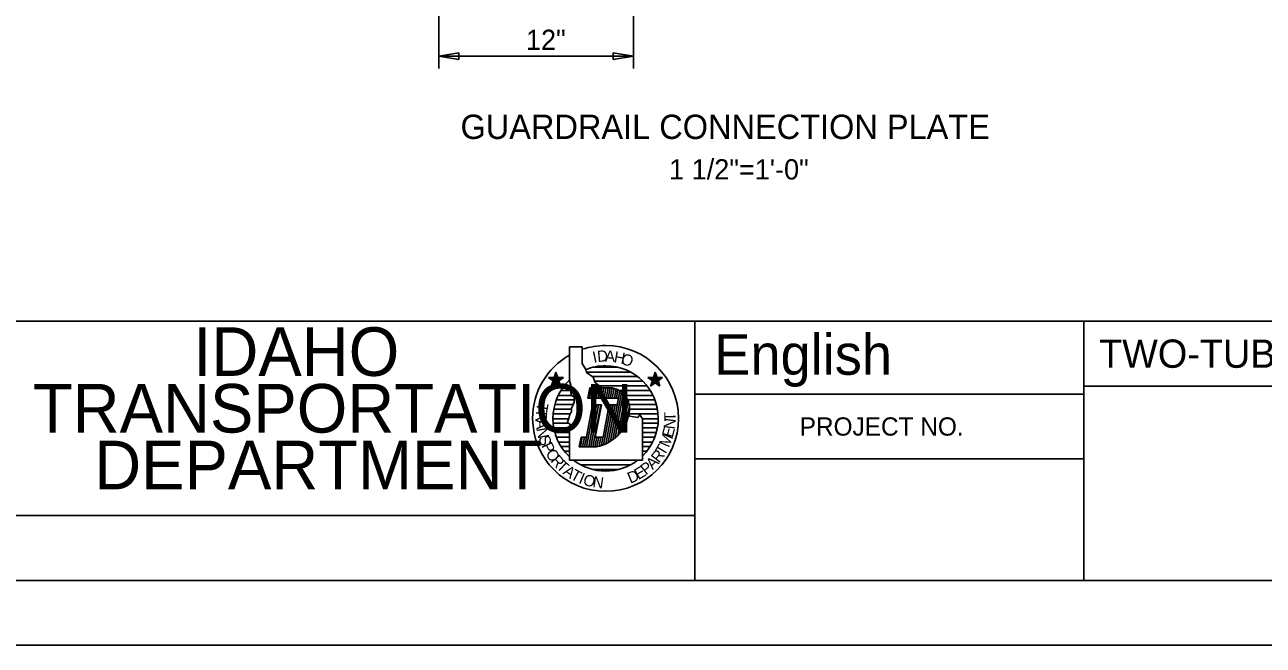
# Model space of a CAD drawing. Extents: x 0 to 22.7, y 0 to 15.7.
# Drawn here: x 9.39 to 15.76, y 0 to 3.19 of the extents above; entities that cross this region are included whole.
import ezdxf

# ---------------------------------------------------------------- set-up
doc = ezdxf.new("R2010")
doc.units = 0
for name, color, linetype in [('BORDER_ANNO_Cutsheet', 7, 'Continuous'), ('BRDG_ANNO_Anno-Sheet', 7, 'Continuous'), ('BRDG_ANNO_General-Notes', 7, 'Continuous')]:
    doc.layers.add(name, color=color, linetype=linetype)

msp = doc.modelspace()

# ---------------------------------------------------------------- linework, layer by layer
at = {"layer": 'BORDER_ANNO_Cutsheet'}
msp.add_lwpolyline([(0, 14.6667), (22.6667, 14.6667), (22.6667, 0), (0, 0)], close=True, dxfattribs=at)
at = {"layer": 'BRDG_ANNO_Anno-Sheet'}
for p, q in [((1, 1.6667), (12.8333, 1.6667)), ((12.8333, 0.3333), (12.8333, 1.6667)), ((12.8333, 1.6667), (22.3333, 1.6667)), ((14.8333, 0.3333), (14.8333, 1.6667)), ((12.1896, 1.3617), (12.1896, 1.5354)), ((12.1896, 1.5354), (12.2554, 1.5354)), ((12.2554, 1.4487), (12.2554, 1.5354)), ((12.1104, 1.3771), (12.1196, 1.4046)), ((12.1196, 1.3492), (12.1196, 1.4046)), ((12.1288, 1.3771), (12.1196, 1.4046)), ((12.2554, 1.4487), (12.2729, 1.4175)), ((12.2729, 1.4175), (12.2762, 1.4033)), ((12.2762, 1.4033), (12.3108, 1.3792)), ((12.2779, 1.4054), (12.5004, 1.4054)), ((12.31, 1.4296), (12.4387, 1.4296)), ((12.6212, 1.3771), (12.6304, 1.4046)), ((12.6304, 1.3492), (12.6304, 1.4046)), ((12.6396, 1.3771), (12.6304, 1.4046)), ((12.1342, 1.36), (12.0817, 1.3771)), ((12.1104, 1.3771), (12.0817, 1.3771)), ((12.105, 1.36), (12.0817, 1.3771)), ((12.1288, 1.3771), (12.0958, 1.3321)), ((12.105, 1.36), (12.0958, 1.3321)), ((12.1196, 1.3492), (12.0958, 1.3321)), ((12.105, 1.36), (12.1579, 1.3771)), ((12.1104, 1.3771), (12.1433, 1.3321)), ((12.1196, 1.3492), (12.1433, 1.3321)), ((12.1288, 1.3771), (12.1579, 1.3771)), ((12.1342, 1.36), (12.1579, 1.3771)), ((12.1342, 1.36), (12.1433, 1.3321)), ((12.1829, 1.3575), (12.1908, 1.3575)), ((12.1962, 1.3375), (12.1896, 1.3617)), ((12.1962, 1.3167), (12.1962, 1.3375)), ((12.31, 1.3817), (12.5379, 1.3817)), ((12.3108, 1.3792), (12.3217, 1.3513)), ((12.3192, 1.3575), (12.5671, 1.3575)), ((12.3217, 1.3513), (12.3562, 1.3237)), ((12.645, 1.36), (12.5921, 1.3771)), ((12.6158, 1.36), (12.5921, 1.3771)), ((12.6212, 1.3771), (12.5921, 1.3771)), ((12.6396, 1.3771), (12.6067, 1.3321)), ((12.6158, 1.36), (12.6067, 1.3321)), ((12.6304, 1.3492), (12.6067, 1.3321)), ((12.6158, 1.36), (12.6683, 1.3771)), ((12.6212, 1.3771), (12.6542, 1.3321)), ((12.6304, 1.3492), (12.6542, 1.3321)), ((12.6396, 1.3771), (12.6683, 1.3771)), ((12.645, 1.36), (12.6683, 1.3771)), ((12.645, 1.36), (12.6542, 1.3321)), ((12.1312, 1.2854), (12.1988, 1.2854)), ((12.1446, 1.3096), (12.195, 1.3096)), ((12.1612, 1.3337), (12.1958, 1.3337)), ((12.1962, 1.2992), (12.1962, 1.3167)), ((12.2, 1.2854), (12.1962, 1.2992)), ((12.2137, 1.2783), (12.2, 1.2854)), ((12.2137, 1.2608), (12.2137, 1.2783)), ((12.2833, 1.2712), (12.2937, 1.3237)), ((12.2929, 1.2712), (12.3025, 1.3237)), ((12.2937, 1.3237), (12.4083, 1.3237)), ((12.3033, 1.2712), (12.3133, 1.3237)), ((12.3142, 1.2712), (12.3238, 1.3237)), ((12.3246, 1.2712), (12.3346, 1.3237)), ((12.335, 1.2712), (12.345, 1.3237)), ((12.3438, 1.3337), (12.5883, 1.3337)), ((12.3458, 1.2712), (12.3554, 1.3237)), ((12.3562, 1.2712), (12.3662, 1.3237)), ((12.3671, 1.2712), (12.3767, 1.3237)), ((12.3775, 1.2712), (12.3875, 1.3237)), ((12.3883, 1.2712), (12.3979, 1.3237)), ((12.3987, 1.2712), (12.4087, 1.3237)), ((12.3996, 1.0496), (12.4479, 1.3079)), ((12.4092, 1.2712), (12.4187, 1.3208)), ((12.4117, 1.0571), (12.4575, 1.3013)), ((12.42, 1.2712), (12.4287, 1.3179)), ((12.4242, 1.0671), (12.4662, 1.2925)), ((12.4304, 1.2712), (12.4383, 1.3133)), ((12.4371, 1.0792), (12.475, 1.2829)), ((12.4458, 1.3096), (12.605, 1.3096)), ((12.4733, 1.2854), (12.6183, 1.2854)), ((12.8333, 1.2917), (14.8333, 1.2917)), ((14.8333, 1.3333), (20.1667, 1.3333)), ((12.1083, 1.2137), (12.1988, 1.2137)), ((12.1137, 1.2375), (12.2075, 1.2375)), ((12.1208, 1.2617), (12.2125, 1.2617)), ((12.2, 1.2192), (12.2067, 1.2333)), ((12.2, 1.2021), (12.2, 1.2192)), ((12.2067, 1.2333), (12.2137, 1.2504)), ((12.2137, 1.2504), (12.2137, 1.2608)), ((12.2762, 1.07), (12.3075, 1.2367)), ((12.2775, 1.0212), (12.3179, 1.2367)), ((12.4408, 1.2712), (12.2833, 1.2712)), ((12.2883, 1.0212), (12.3287, 1.2367)), ((12.2988, 1.0212), (12.3392, 1.2367)), ((12.3075, 1.2367), (12.3533, 1.2367)), ((12.3096, 1.0212), (12.35, 1.2367)), ((12.3533, 1.2367), (12.3221, 1.07)), ((12.3625, 1.07), (12.3937, 1.2367)), ((12.3646, 1.0317), (12.4029, 1.2367)), ((12.3758, 1.0367), (12.4133, 1.2367)), ((12.3875, 1.0421), (12.4242, 1.2367)), ((12.3937, 1.2367), (12.4346, 1.2367)), ((12.4346, 1.2367), (12.4408, 1.2712)), ((12.4504, 1.0933), (12.4833, 1.2708)), ((12.4646, 1.1125), (12.4912, 1.2546)), ((12.4812, 1.145), (12.4971, 1.23)), ((12.4883, 1.2617), (12.6288, 1.2617)), ((12.4962, 1.2375), (12.6363, 1.2375)), ((12.4983, 1.2137), (12.6417, 1.2137)), ((12.1042, 1.1654), (12.185, 1.1654)), ((12.105, 1.1896), (12.1937, 1.1896)), ((12.1792, 1.15), (12.1858, 1.1671)), ((12.1896, 1.1396), (12.1792, 1.15)), ((12.1858, 1.1671), (12.1896, 1.1812)), ((12.1896, 1.1812), (12.2, 1.2021)), ((12.4938, 1.185), (12.4987, 1.1775)), ((12.495, 1.1896), (12.645, 1.1896)), ((12.4987, 1.1775), (12.5196, 1.1742)), ((12.5196, 1.1742), (12.5404, 1.1708)), ((12.5404, 1.1708), (12.5508, 1.1846)), ((12.5508, 1.1846), (12.5646, 1.1638)), ((12.5633, 1.1654), (12.6458, 1.1654)), ((12.5646, 1.1638), (12.5646, 0.9517)), ((12.1054, 1.1417), (12.1875, 1.1417)), ((12.1087, 1.1175), (12.1988, 1.1175)), ((12.1142, 1.0938), (12.1892, 1.0938)), ((12.1962, 1.1292), (12.1896, 1.1396)), ((12.1896, 1.1013), (12.2, 1.1117)), ((12.1896, 0.9517), (12.1896, 1.1013)), ((12.2, 1.1221), (12.1962, 1.1292)), ((12.2, 1.1117), (12.2, 1.1221)), ((12.5646, 1.1175), (12.6412, 1.1175)), ((12.5646, 1.0938), (12.6358, 1.0938)), ((12.565, 1.1417), (12.6446, 1.1417)), ((12.1225, 1.0696), (12.1883, 1.0696)), ((12.1329, 1.0454), (12.1883, 1.0454)), ((12.1467, 1.0217), (12.1887, 1.0217)), ((12.2396, 1.0212), (12.2487, 1.07)), ((12.3283, 1.0212), (12.2396, 1.0212)), ((12.2458, 1.0212), (12.255, 1.07)), ((12.2487, 1.07), (12.2762, 1.07)), ((12.2567, 1.0212), (12.2658, 1.07)), ((12.2671, 1.0212), (12.2762, 1.07)), ((12.32, 1.0212), (12.3292, 1.07)), ((12.3221, 1.07), (12.3625, 1.07)), ((12.3308, 1.0217), (12.34, 1.07)), ((12.3421, 1.0246), (12.3504, 1.07)), ((12.3533, 1.0279), (12.3608, 1.07)), ((12.5646, 1.0696), (12.6275, 1.0696)), ((12.5646, 1.0454), (12.6167, 1.0454)), ((12.5646, 1.0217), (12.6033, 1.0217)), ((12.1638, 0.9975), (12.1883, 0.9975)), ((12.185, 0.9738), (12.1892, 0.9738)), ((12.5646, 0.9975), (12.5867, 0.9975)), ((12.8333, 0.9583), (14.8333, 0.9583)), ((12.5646, 0.9517), (12.1896, 0.9517)), ((12.5004, 0.9275), (12.2479, 0.9275)), ((12.4392, 0.9037), (12.3117, 0.9037)), ((9.3333, 0.6667), (12.8333, 0.6667))]:
    msp.add_line(p, q, dxfattribs=at)
msp.add_lwpolyline([(1, 14.3333), (22.3333, 14.3333), (22.3333, 0.3333), (1, 0.3333)], close=True, dxfattribs=at)
for centre, radius, start, end in [((12.375, 1.1667), 0.375, 90, 108.596), ((12.375, 1.1667), 0.375, 0, 90), ((12.375, 1.1667), 0.375, 119.63312, 180), ((12.375, 1.1667), 0.2708, 90, 112.14518), ((12.375, 1.1667), 0.2708, 0, 90), ((12.375, 1.1667), 0.2708, 133.19257, 180), ((12.3888, 1.2161), 0.1094, 343.49805, 79.73615), ((12.375, 1.1667), 0.375, 180, 270), ((12.375, 1.1667), 0.2708, 180.26444, 226.79463), ((12.2899, 1.2255), 0.2078, 280.64795, 348.77185), ((12.375, 1.1667), 0.375, 270, 0), ((12.375, 1.1667), 0.2708, 314.427, 0), ((12.375, 1.1667), 0.2708, 232.5658, 270), ((12.375, 1.1667), 0.2708, 270, 307.45359)]:
    msp.add_arc(centre, radius, start, end, dxfattribs=at)
at = {"layer": 'BRDG_ANNO_General-Notes'}
for p, q in [((11.5179, 2.9662), (11.5179, 3.7347)), ((12.5179, 2.9662), (12.5179, 3.6642)), ((11.6212, 3.0479), (11.5179, 3.0307)), ((12.5179, 3.0307), (11.5179, 3.0307)), ((11.5179, 3.0307), (11.6212, 3.0134)), ((11.6212, 3.0134), (11.6212, 3.0479)), ((12.4146, 3.0479), (12.4146, 3.0134)), ((12.5179, 3.0307), (12.4146, 3.0479)), ((12.4146, 3.0134), (12.5179, 3.0307))]:
    msp.add_line(p, q, dxfattribs=at)

# ---------------------------------------------------------------- texts
at = {"layer": 'BRDG_ANNO_Anno-Sheet'}
for s, height, p in [('IDAHO', 0.25, (10.2558, 1.3854)), ('English', 0.20833, (12.9337, 1.3912)), ('TWO-TUBE CURB MOUNT RAIL W/ THRIE BEAM END CONNECTION - SHT. 2 OF 2', 0.145418, (14.9116, 1.4271)), ('TRANSPORTATION', 0.25, (9.4313, 1.0938)), ('PROJECT NO.', 0.09375, (13.3728, 1.0783)), ('DEPARTMENT', 0.25, (9.7462, 0.8021))]:
    msp.add_text(s, height=height, dxfattribs=at).set_placement(p)
for s, rotation, p in [('I', 11.95188, (12.3146, 1.4521)), ('D', 5.21184, (12.3342, 1.4563)), ('A', 357.8718, (12.3712, 1.4587)), ('H', 349.63177, (12.4146, 1.4558)), ('O', 342.19173, (12.4496, 1.4487)), ('T', 259.42648, (12.0254, 1.2504)), ('R', 266.0275, (12.0175, 1.205)), ('A', 273.76404, (12.0154, 1.1604)), ('N', 83.19321, (12.73, 1.1087)), ('T', 90.49256, (12.7346, 1.1529)), ('N', 280.37584, (12.0192, 1.1142)), ('M', 67.71394, (12.7004, 1.0137)), ('E', 75.61046, (12.7196, 1.0646)), ('S', 287.92792, (12.0287, 1.0692)), ('P', 295.49755, (12.0437, 1.0271)), ('T', 59.03624, (12.6758, 0.97)), ('O', 302.64464, (12.0637, 0.9867)), ('R', 309.90789, (12.0892, 0.9483)), ('T', 317.1211, (12.1183, 0.9142)), ('A', 45, (12.6171, 0.9004)), ('R', 52.33438, (12.6492, 0.9342)), ('A', 324.63754, (12.1521, 0.8837)), ('T', 331.75026, (12.1896, 0.8579)), ('D', 22.98872, (12.5021, 0.8304)), ('E', 30.54757, (12.5437, 0.8492)), ('P', 37.66562, (12.5821, 0.8729)), ('I', 337.0213, (12.2329, 0.8358)), ('O', 343.32869, (12.255, 0.8271)), ('N', 351.65981, (12.3058, 0.8133))]:
    msp.add_text(s, height=0.0579, rotation=rotation, dxfattribs=at).set_placement(p)
at = {"layer": 'BRDG_ANNO_General-Notes'}
for s, height, p in [('12"', 0.10417, (11.9655, 3.0619)), ('GUARDRAIL CONNECTION PLATE', 0.125, (11.6292, 2.6041)), ('1 1/2"=1\'-0"', 0.104167, (12.7012, 2.3957))]:
    msp.add_text(s, height=height, dxfattribs=at).set_placement(p)

doc.saveas('drawing.dxf')
